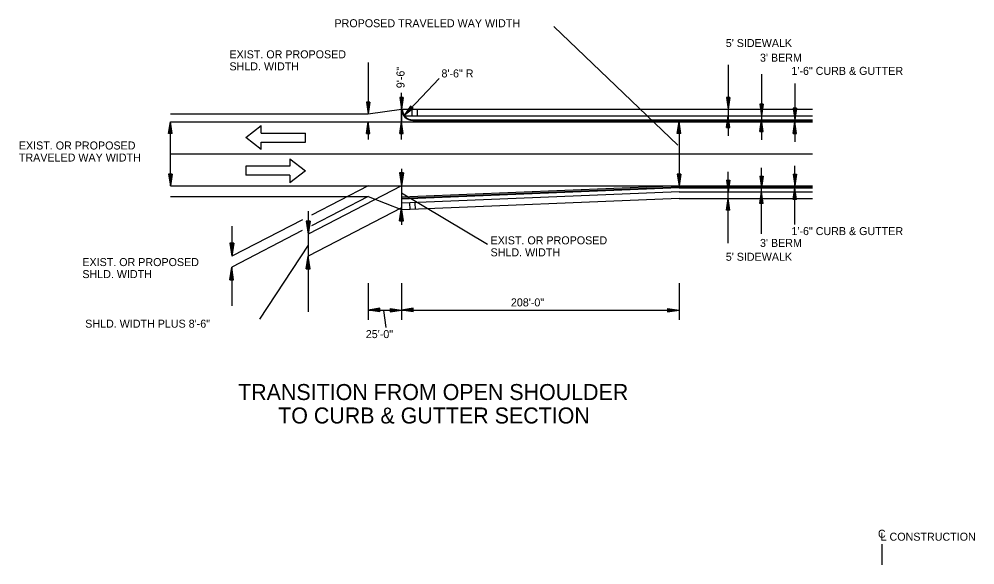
# Model space of a CAD drawing. Extents: x 635488 to 635865, y 290537 to 290973.
# Drawn here: x 635637.4 to 635709, y 290700.2 to 290741.1 of the extents above; entities that cross this region are included whole.
import ezdxf

# ---------------------------------------------------------------- set-up
doc = ezdxf.new("R2010")
doc.units = 0
for name, color, linetype in [('Default', 7, 'Continuous'), ('E_Existing ROW', 7, 'Continuous'), ('Level 13', 7, 'Continuous'), ('R_Border', 7, 'Continuous')]:
    doc.layers.add(name, color=color, linetype=linetype)

msp = doc.modelspace()

# ---------------------------------------------------------------- linework, layer by layer
at = {"layer": 'Default'}
for p, q in [((635677.431, 290740.568), (635686.72, 290731.689)), ((635663.524, 290737.876), (635663.524, 290734.024)), ((635690.499, 290737.702), (635690.499, 290732.374)), ((635692.999, 290737.002), (635692.999, 290732.074)), ((635695.499, 290736.302), (635695.499, 290731.924)), ((635663.524, 290734.024), (635666.024, 290734.374)), ((635666.024, 290734.374), (635696.824, 290734.374)), ((635666.787, 290734.374), (635666.787, 290733.874)), ((635667.187, 290734.374), (635667.187, 290733.874)), ((635648.699, 290734.024), (635663.524, 290734.024)), ((635648.699, 290733.424), (635696.824, 290733.424)), ((635648.699, 290728.624), (635648.699, 290733.424)), ((635663.524, 290733.424), (635663.524, 290732.112)), ((635666.187, 290733.874), (635696.824, 290733.874)), ((635666.874, 290733.574), (635696.824, 290733.574)), ((635666.874, 290733.524), (635696.824, 290733.524)), ((635648.699, 290731.024), (635696.824, 290731.024)), ((635692.999, 290725.045), (635692.999, 290729.974)), ((635695.499, 290725.745), (635695.499, 290730.124)), ((635690.499, 290724.345), (635690.499, 290729.674)), ((635648.699, 290728.624), (635686.824, 290728.624)), ((635686.824, 290728.624), (635666.02, 290727.773)), ((635686.824, 290728.524), (635666.024, 290727.674)), ((635686.824, 290728.473), (635666.026, 290727.624)), ((635686.822, 290728.624), (635696.824, 290728.624)), ((635686.824, 290728.524), (635696.824, 290728.524)), ((635686.824, 290728.474), (635696.824, 290728.474)), ((635648.699, 290727.824), (635663.524, 290727.824)), ((635663.524, 290727.824), (635666.059, 290726.824)), ((635686.824, 290728.173), (635666.038, 290727.324)), ((635686.824, 290728.174), (635696.824, 290728.174)), ((635686.824, 290727.673), (635666.059, 290726.824)), ((635666.658, 290726.849), (635666.638, 290727.348)), ((635667.058, 290726.865), (635667.038, 290727.365)), ((635686.824, 290727.674), (635696.824, 290727.674)), ((635663.524, 290721.342), (635663.524, 290718.581)), ((635666.024, 290721.342), (635666.024, 290718.581)), ((635686.824, 290721.342), (635686.824, 290718.581)), ((635663.524, 290719.323), (635666.024, 290719.323)), ((635664.861, 290718.01), (635664.707, 290719.285)), ((635666.024, 290719.323), (635686.824, 290719.323))]:
    msp.add_line(p, q, dxfattribs=at)
for radius in [0.85, 0.8]:
    msp.add_arc((635666.874, 290734.374), radius, 180, 270, dxfattribs=at)
at = {"layer": 'E_Existing ROW'}
for p, q in [((635668.836, 290736.674), (635666.187, 290733.874)), ((635666.024, 290732.112), (635666.024, 290735.608)), ((635663.393, 290734.898), (635663.524, 290734.024)), ((635663.655, 290734.898), (635663.393, 290734.898)), ((635663.414, 290734.898), (635663.524, 290734.169)), ((635663.437, 290734.898), (635663.524, 290734.32)), ((635663.459, 290734.898), (635663.524, 290734.466)), ((635663.481, 290734.898), (635663.524, 290734.614)), ((635663.504, 290734.898), (635663.524, 290734.76)), ((635663.655, 290734.898), (635663.524, 290734.024)), ((635663.567, 290734.898), (635663.524, 290734.614)), ((635663.611, 290734.898), (635663.524, 290734.32)), ((635663.634, 290734.898), (635663.524, 290734.169)), ((635663.59, 290734.898), (635663.524, 290734.466)), ((635663.544, 290734.898), (635663.524, 290734.76)), ((635665.893, 290735.248), (635666.024, 290734.374)), ((635666.155, 290735.248), (635665.893, 290735.248)), ((635665.914, 290735.248), (635666.024, 290734.519)), ((635665.937, 290735.248), (635666.024, 290734.67)), ((635665.959, 290735.248), (635666.024, 290734.816)), ((635665.981, 290735.248), (635666.024, 290734.964)), ((635666.004, 290735.248), (635666.024, 290735.11)), ((635666.155, 290735.248), (635666.024, 290734.374)), ((635666.067, 290735.248), (635666.024, 290734.964)), ((635666.111, 290735.248), (635666.024, 290734.67)), ((635666.134, 290735.248), (635666.024, 290734.519)), ((635666.09, 290735.248), (635666.024, 290734.816)), ((635666.044, 290735.248), (635666.024, 290735.11)), ((635690.368, 290735.248), (635690.499, 290734.374)), ((635690.63, 290735.248), (635690.368, 290735.248)), ((635690.39, 290735.248), (635690.499, 290734.519)), ((635690.412, 290735.248), (635690.499, 290734.67)), ((635690.434, 290735.248), (635690.499, 290734.816)), ((635690.457, 290735.248), (635690.499, 290734.964)), ((635690.479, 290735.248), (635690.499, 290735.11)), ((635690.63, 290735.248), (635690.499, 290734.374)), ((635690.542, 290735.248), (635690.499, 290734.964)), ((635690.586, 290735.248), (635690.499, 290734.67)), ((635690.609, 290735.248), (635690.499, 290734.519)), ((635690.565, 290735.248), (635690.499, 290734.816)), ((635690.519, 290735.248), (635690.499, 290735.11)), ((635666.024, 290734.374), (635666.024, 290733.424)), ((635666.692, 290734.598), (635666.186, 290733.873)), ((635666.882, 290734.418), (635666.186, 290733.873)), ((635666.708, 290734.583), (635666.286, 290733.978)), ((635666.867, 290734.433), (635666.286, 290733.978)), ((635666.724, 290734.568), (635666.39, 290734.088)), ((635666.85, 290734.448), (635666.39, 290734.088)), ((635666.74, 290734.553), (635666.491, 290734.195)), ((635666.835, 290734.463), (635666.491, 290734.195)), ((635666.756, 290734.537), (635666.593, 290734.302)), ((635666.818, 290734.479), (635666.593, 290734.302)), ((635666.882, 290734.418), (635666.692, 290734.598)), ((635666.773, 290734.522), (635666.692, 290734.408)), ((635666.802, 290734.494), (635666.692, 290734.408)), ((635692.868, 290734.748), (635692.999, 290733.874)), ((635693.13, 290734.748), (635692.868, 290734.748)), ((635692.89, 290734.748), (635692.999, 290734.019)), ((635692.912, 290734.748), (635692.999, 290734.17)), ((635692.934, 290734.748), (635692.999, 290734.316)), ((635692.957, 290734.748), (635692.999, 290734.464)), ((635692.979, 290734.748), (635692.999, 290734.61)), ((635693.13, 290734.748), (635692.999, 290733.874)), ((635693.042, 290734.748), (635692.999, 290734.464)), ((635693.086, 290734.748), (635692.999, 290734.17)), ((635693.109, 290734.748), (635692.999, 290734.019)), ((635693.065, 290734.748), (635692.999, 290734.316)), ((635693.019, 290734.748), (635692.999, 290734.61)), ((635695.368, 290734.448), (635695.499, 290733.574)), ((635695.63, 290734.448), (635695.368, 290734.448)), ((635695.39, 290734.448), (635695.499, 290733.719)), ((635695.412, 290734.448), (635695.499, 290733.87)), ((635695.434, 290734.448), (635695.499, 290734.016)), ((635695.457, 290734.448), (635695.499, 290734.164)), ((635695.479, 290734.448), (635695.499, 290734.31)), ((635695.63, 290734.448), (635695.499, 290733.574)), ((635695.542, 290734.448), (635695.499, 290734.164)), ((635695.586, 290734.448), (635695.499, 290733.87)), ((635695.609, 290734.448), (635695.499, 290733.719)), ((635695.565, 290734.448), (635695.499, 290734.016)), ((635695.519, 290734.448), (635695.499, 290734.31)), ((635648.568, 290732.549), (635648.699, 290733.424)), ((635648.83, 290732.549), (635648.699, 290733.424)), ((635663.393, 290732.549), (635663.524, 290733.424)), ((635663.655, 290732.549), (635663.524, 290733.424)), ((635665.893, 290732.549), (635666.024, 290733.424)), ((635666.155, 290732.549), (635666.024, 290733.424)), ((635686.693, 290732.549), (635686.824, 290733.424)), ((635686.824, 290733.424), (635686.824, 290728.624)), ((635686.955, 290732.549), (635686.824, 290733.424)), ((635690.368, 290732.999), (635690.499, 290733.874)), ((635690.39, 290732.999), (635690.499, 290733.728)), ((635690.412, 290732.999), (635690.499, 290733.577)), ((635690.434, 290732.999), (635690.499, 290733.431)), ((635690.63, 290732.999), (635690.499, 290733.874)), ((635690.609, 290732.999), (635690.499, 290733.728)), ((635690.586, 290732.999), (635690.499, 290733.577)), ((635690.565, 290732.999), (635690.499, 290733.431)), ((635692.868, 290732.699), (635692.999, 290733.574)), ((635692.89, 290732.699), (635692.999, 290733.428)), ((635693.13, 290732.699), (635692.999, 290733.574)), ((635693.109, 290732.699), (635692.999, 290733.428)), ((635695.368, 290732.549), (635695.499, 290733.424)), ((635695.63, 290732.549), (635695.499, 290733.424)), ((635648.589, 290732.549), (635648.699, 290733.278)), ((635648.612, 290732.549), (635648.699, 290733.127)), ((635648.633, 290732.549), (635648.699, 290732.981)), ((635648.656, 290732.549), (635648.699, 290732.833)), ((635648.808, 290732.549), (635648.699, 290733.278)), ((635648.785, 290732.549), (635648.699, 290733.127)), ((635648.764, 290732.549), (635648.699, 290732.981)), ((635648.741, 290732.549), (635648.699, 290732.833)), ((635654.341, 290732.251), (635655.509, 290733.151)), ((635655.509, 290732.588), (635655.509, 290733.151)), ((635663.414, 290732.549), (635663.524, 290733.278)), ((635663.437, 290732.549), (635663.524, 290733.127)), ((635663.459, 290732.549), (635663.524, 290732.981)), ((635663.481, 290732.549), (635663.524, 290732.833)), ((635663.634, 290732.549), (635663.524, 290733.278)), ((635663.611, 290732.549), (635663.524, 290733.127)), ((635663.59, 290732.549), (635663.524, 290732.981)), ((635663.567, 290732.549), (635663.524, 290732.833)), ((635665.914, 290732.549), (635666.024, 290733.278)), ((635665.937, 290732.549), (635666.024, 290733.127)), ((635665.959, 290732.549), (635666.024, 290732.981)), ((635665.981, 290732.549), (635666.024, 290732.833)), ((635666.134, 290732.549), (635666.024, 290733.278)), ((635666.111, 290732.549), (635666.024, 290733.127)), ((635666.09, 290732.549), (635666.024, 290732.981)), ((635666.067, 290732.549), (635666.024, 290732.833)), ((635686.714, 290732.549), (635686.824, 290733.278)), ((635686.737, 290732.549), (635686.824, 290733.127)), ((635686.759, 290732.549), (635686.824, 290732.981)), ((635686.781, 290732.549), (635686.824, 290732.833)), ((635686.934, 290732.549), (635686.824, 290733.278)), ((635686.911, 290732.549), (635686.824, 290733.127)), ((635686.89, 290732.549), (635686.824, 290732.981)), ((635686.867, 290732.549), (635686.824, 290732.833)), ((635690.368, 290732.999), (635690.63, 290732.999)), ((635690.457, 290732.999), (635690.499, 290733.283)), ((635690.479, 290732.999), (635690.499, 290733.137)), ((635690.542, 290732.999), (635690.499, 290733.283)), ((635690.519, 290732.999), (635690.499, 290733.137)), ((635692.868, 290732.699), (635693.13, 290732.699)), ((635692.912, 290732.699), (635692.999, 290733.277)), ((635692.934, 290732.699), (635692.999, 290733.131)), ((635692.957, 290732.699), (635692.999, 290732.983)), ((635692.979, 290732.699), (635692.999, 290732.837)), ((635693.086, 290732.699), (635692.999, 290733.277)), ((635693.065, 290732.699), (635692.999, 290733.131)), ((635693.042, 290732.699), (635692.999, 290732.983)), ((635693.019, 290732.699), (635692.999, 290732.837)), ((635695.39, 290732.549), (635695.499, 290733.278)), ((635695.412, 290732.549), (635695.499, 290733.127)), ((635695.434, 290732.549), (635695.499, 290732.981)), ((635695.457, 290732.549), (635695.499, 290732.833)), ((635695.609, 290732.549), (635695.499, 290733.278)), ((635695.586, 290732.549), (635695.499, 290733.127)), ((635695.565, 290732.549), (635695.499, 290732.981)), ((635695.542, 290732.549), (635695.499, 290732.833)), ((635648.83, 290732.549), (635648.568, 290732.549)), ((635648.679, 290732.549), (635648.699, 290732.687)), ((635648.718, 290732.549), (635648.699, 290732.687)), ((635655.509, 290731.351), (635654.341, 290732.251)), ((635655.509, 290732.588), (635658.819, 290732.588)), ((635658.819, 290731.913), (635658.819, 290732.588)), ((635663.393, 290732.549), (635663.655, 290732.549)), ((635663.504, 290732.549), (635663.524, 290732.687)), ((635663.544, 290732.549), (635663.524, 290732.687)), ((635665.893, 290732.549), (635666.155, 290732.549)), ((635666.004, 290732.549), (635666.024, 290732.687)), ((635666.044, 290732.549), (635666.024, 290732.687)), ((635686.955, 290732.549), (635686.693, 290732.549)), ((635686.804, 290732.549), (635686.824, 290732.687)), ((635686.844, 290732.549), (635686.824, 290732.687)), ((635695.368, 290732.549), (635695.63, 290732.549)), ((635695.479, 290732.549), (635695.499, 290732.687)), ((635695.519, 290732.549), (635695.499, 290732.687)), ((635655.509, 290731.913), (635658.819, 290731.913)), ((635655.509, 290731.351), (635655.509, 290731.913)), ((635657.651, 290730.658), (635657.651, 290730.096)), ((635657.651, 290730.658), (635658.819, 290729.758)), ((635657.651, 290730.096), (635654.341, 290730.096)), ((635654.341, 290730.096), (635654.341, 290729.421)), ((635666.02, 290729.906), (635666.02, 290728.624)), ((635648.568, 290729.498), (635648.699, 290728.624)), ((635648.83, 290729.498), (635648.568, 290729.498)), ((635648.589, 290729.498), (635648.699, 290728.769)), ((635648.612, 290729.498), (635648.699, 290728.92)), ((635648.633, 290729.498), (635648.699, 290729.066)), ((635648.656, 290729.498), (635648.699, 290729.214)), ((635648.679, 290729.498), (635648.699, 290729.36)), ((635648.83, 290729.498), (635648.699, 290728.624)), ((635648.741, 290729.498), (635648.699, 290729.214)), ((635648.785, 290729.498), (635648.699, 290728.92)), ((635648.808, 290729.498), (635648.699, 290728.769)), ((635648.764, 290729.498), (635648.699, 290729.066)), ((635648.718, 290729.498), (635648.699, 290729.36)), ((635657.651, 290729.421), (635654.341, 290729.421)), ((635658.819, 290729.758), (635657.651, 290728.858)), ((635657.651, 290729.421), (635657.651, 290728.858)), ((635665.873, 290729.606), (635666.02, 290728.624)), ((635666.167, 290729.606), (635665.873, 290729.606)), ((635665.897, 290729.606), (635666.02, 290728.787)), ((635665.922, 290729.606), (635666.02, 290728.956)), ((635665.946, 290729.606), (635666.02, 290729.121)), ((635665.972, 290729.606), (635666.02, 290729.287)), ((635665.998, 290729.606), (635666.02, 290729.451)), ((635666.167, 290729.606), (635666.02, 290728.624)), ((635666.068, 290729.606), (635666.02, 290729.287)), ((635666.118, 290729.606), (635666.02, 290728.956)), ((635666.143, 290729.606), (635666.02, 290728.787)), ((635666.094, 290729.606), (635666.02, 290729.121)), ((635666.042, 290729.606), (635666.02, 290729.451)), ((635686.693, 290729.498), (635686.824, 290728.624)), ((635686.955, 290729.498), (635686.693, 290729.498)), ((635686.714, 290729.498), (635686.824, 290728.769)), ((635686.737, 290729.498), (635686.824, 290728.92)), ((635686.759, 290729.498), (635686.824, 290729.066)), ((635686.781, 290729.498), (635686.824, 290729.215)), ((635686.804, 290729.498), (635686.824, 290729.36)), ((635686.955, 290729.498), (635686.824, 290728.624)), ((635686.867, 290729.498), (635686.824, 290729.215)), ((635686.911, 290729.498), (635686.824, 290728.92)), ((635686.934, 290729.498), (635686.824, 290728.769)), ((635686.89, 290729.498), (635686.824, 290729.066)), ((635686.844, 290729.498), (635686.824, 290729.36)), ((635692.868, 290729.348), (635692.999, 290728.474)), ((635692.868, 290729.348), (635693.13, 290729.348)), ((635692.89, 290729.348), (635692.999, 290728.619)), ((635692.912, 290729.348), (635692.999, 290728.77)), ((635692.934, 290729.348), (635692.999, 290728.916)), ((635692.957, 290729.348), (635692.999, 290729.064)), ((635692.979, 290729.348), (635692.999, 290729.21)), ((635693.13, 290729.348), (635692.999, 290728.474)), ((635693.042, 290729.348), (635692.999, 290729.064)), ((635693.086, 290729.348), (635692.999, 290728.77)), ((635693.109, 290729.348), (635692.999, 290728.619)), ((635693.065, 290729.348), (635692.999, 290728.916)), ((635693.019, 290729.348), (635692.999, 290729.21)), ((635695.368, 290729.498), (635695.499, 290728.624)), ((635695.368, 290729.498), (635695.63, 290729.498)), ((635695.39, 290729.498), (635695.499, 290728.769)), ((635695.412, 290729.498), (635695.499, 290728.92)), ((635695.434, 290729.498), (635695.499, 290729.066)), ((635695.457, 290729.498), (635695.499, 290729.214)), ((635695.479, 290729.498), (635695.499, 290729.36)), ((635695.63, 290729.498), (635695.499, 290728.624)), ((635695.542, 290729.498), (635695.499, 290729.214)), ((635695.586, 290729.498), (635695.499, 290728.92)), ((635695.609, 290729.498), (635695.499, 290728.769)), ((635695.565, 290729.498), (635695.499, 290729.066)), ((635695.519, 290729.498), (635695.499, 290729.36)), ((635666.02, 290728.624), (635659.018, 290725.012)), ((635663.519, 290728.624), (635659.275, 290726.434)), ((635666.02, 290728.624), (635666.02, 290725.714)), ((635690.368, 290729.048), (635690.499, 290728.174)), ((635690.368, 290729.048), (635690.63, 290729.048)), ((635690.39, 290729.048), (635690.499, 290728.319)), ((635690.412, 290729.048), (635690.499, 290728.47)), ((635690.434, 290729.048), (635690.499, 290728.616)), ((635690.457, 290729.048), (635690.499, 290728.764)), ((635690.479, 290729.048), (635690.499, 290728.91)), ((635690.63, 290729.048), (635690.499, 290728.174)), ((635690.542, 290729.048), (635690.499, 290728.764)), ((635690.586, 290729.048), (635690.499, 290728.47)), ((635690.609, 290729.048), (635690.499, 290728.319)), ((635690.565, 290729.048), (635690.499, 290728.616)), ((635690.519, 290729.048), (635690.499, 290728.91)), ((635695.368, 290727.599), (635695.499, 290728.474)), ((635695.63, 290727.599), (635695.499, 290728.474)), ((635663.519, 290727.824), (635659.279, 290725.637)), ((635666.02, 290728.109), (635672.455, 290724.272)), ((635692.868, 290727.299), (635692.999, 290728.174)), ((635692.89, 290727.299), (635692.999, 290728.028)), ((635692.912, 290727.299), (635692.999, 290727.877)), ((635692.934, 290727.299), (635692.999, 290727.731)), ((635693.13, 290727.299), (635692.999, 290728.174)), ((635693.109, 290727.299), (635692.999, 290728.028)), ((635693.086, 290727.299), (635692.999, 290727.877)), ((635693.065, 290727.299), (635692.999, 290727.731)), ((635695.39, 290727.599), (635695.499, 290728.328)), ((635695.412, 290727.599), (635695.499, 290728.177)), ((635695.434, 290727.599), (635695.499, 290728.031)), ((635695.457, 290727.599), (635695.499, 290727.883)), ((635695.479, 290727.599), (635695.499, 290727.737)), ((635695.609, 290727.599), (635695.499, 290728.328)), ((635695.586, 290727.599), (635695.499, 290728.177)), ((635695.565, 290727.599), (635695.499, 290728.031)), ((635695.542, 290727.599), (635695.499, 290727.883)), ((635695.519, 290727.599), (635695.499, 290727.737)), ((635666.02, 290726.972), (635659.018, 290723.36)), ((635665.876, 290726.012), (635666.02, 290726.972)), ((635666.164, 290726.012), (635666.02, 290726.972)), ((635690.368, 290726.799), (635690.499, 290727.674)), ((635690.39, 290726.799), (635690.499, 290727.528)), ((635690.412, 290726.799), (635690.499, 290727.377)), ((635690.434, 290726.799), (635690.499, 290727.231)), ((635690.457, 290726.799), (635690.499, 290727.083)), ((635690.63, 290726.799), (635690.499, 290727.674)), ((635690.609, 290726.799), (635690.499, 290727.528)), ((635690.586, 290726.799), (635690.499, 290727.377)), ((635690.565, 290726.799), (635690.499, 290727.231)), ((635690.542, 290726.799), (635690.499, 290727.083)), ((635693.13, 290727.299), (635692.868, 290727.299)), ((635692.957, 290727.299), (635692.999, 290727.583)), ((635692.979, 290727.299), (635692.999, 290727.437)), ((635693.042, 290727.299), (635692.999, 290727.583)), ((635693.019, 290727.299), (635692.999, 290727.437)), ((635695.63, 290727.599), (635695.368, 290727.599)), ((635659.018, 290726.729), (635659.018, 290722.102)), ((635665.9, 290726.012), (635666.02, 290726.812)), ((635665.924, 290726.012), (635666.02, 290726.647)), ((635665.948, 290726.012), (635666.02, 290726.487)), ((635665.974, 290726.012), (635666.02, 290726.324)), ((635666.14, 290726.012), (635666.02, 290726.812)), ((635666.116, 290726.012), (635666.02, 290726.647)), ((635666.092, 290726.012), (635666.02, 290726.487)), ((635666.066, 290726.012), (635666.02, 290726.324)), ((635690.63, 290726.799), (635690.368, 290726.799)), ((635690.479, 290726.799), (635690.499, 290726.937)), ((635690.519, 290726.799), (635690.499, 290726.937)), ((635658.603, 290726.088), (635653.293, 290723.349)), ((635653.293, 290725.614), (635653.293, 290723.349)), ((635658.87, 290725.994), (635659.018, 290725.012)), ((635659.165, 290725.994), (635658.87, 290725.994)), ((635658.894, 290725.994), (635659.018, 290725.175)), ((635658.92, 290725.994), (635659.018, 290725.344)), ((635658.944, 290725.994), (635659.018, 290725.509)), ((635658.97, 290725.994), (635659.018, 290725.675)), ((635658.995, 290725.994), (635659.018, 290725.839)), ((635659.165, 290725.994), (635659.018, 290725.012)), ((635659.066, 290725.994), (635659.018, 290725.675)), ((635659.115, 290725.994), (635659.018, 290725.344)), ((635659.141, 290725.994), (635659.018, 290725.175)), ((635659.091, 290725.994), (635659.018, 290725.509)), ((635659.04, 290725.994), (635659.018, 290725.839)), ((635665.876, 290726.012), (635666.164, 290726.012)), ((635665.998, 290726.012), (635666.02, 290726.164)), ((635666.042, 290726.012), (635666.02, 290726.164)), ((635658.586, 290725.279), (635653.293, 290722.549)), ((635653.146, 290724.331), (635653.293, 290723.349)), ((635653.441, 290724.331), (635653.146, 290724.331)), ((635653.17, 290724.331), (635653.293, 290723.512)), ((635653.196, 290724.331), (635653.293, 290723.682)), ((635653.22, 290724.331), (635653.293, 290723.847)), ((635653.245, 290724.331), (635653.293, 290724.013)), ((635653.271, 290724.331), (635653.293, 290724.176)), ((635653.441, 290724.331), (635653.293, 290723.349)), ((635653.341, 290724.331), (635653.293, 290724.013)), ((635653.391, 290724.331), (635653.293, 290723.682)), ((635653.417, 290724.331), (635653.293, 290723.512)), ((635653.367, 290724.331), (635653.293, 290723.847)), ((635653.316, 290724.331), (635653.293, 290724.176)), ((635659.018, 290724.195), (635655.377, 290718.63)), ((635658.874, 290722.4), (635659.018, 290723.36)), ((635658.898, 290722.4), (635659.018, 290723.2)), ((635658.922, 290722.4), (635659.018, 290723.035)), ((635658.946, 290722.4), (635659.018, 290722.875)), ((635658.971, 290722.4), (635659.018, 290722.712)), ((635659.162, 290722.4), (635659.018, 290723.36)), ((635659.138, 290722.4), (635659.018, 290723.2)), ((635659.114, 290722.4), (635659.018, 290723.035)), ((635659.09, 290722.4), (635659.018, 290722.875)), ((635659.064, 290722.4), (635659.018, 290722.712)), ((635653.149, 290721.589), (635653.293, 290722.549)), ((635653.173, 290721.589), (635653.293, 290722.389)), ((635653.197, 290721.589), (635653.293, 290722.224)), ((635653.221, 290721.589), (635653.293, 290722.064)), ((635653.293, 290722.549), (635653.293, 290719.63)), ((635653.437, 290721.589), (635653.293, 290722.549)), ((635653.413, 290721.589), (635653.293, 290722.389)), ((635653.389, 290721.589), (635653.293, 290722.224)), ((635653.365, 290721.589), (635653.293, 290722.064)), ((635658.874, 290722.4), (635659.162, 290722.4)), ((635658.995, 290722.4), (635659.018, 290722.552)), ((635659.04, 290722.4), (635659.018, 290722.552)), ((635659.018, 290722.102), (635659.018, 290719.183)), ((635653.149, 290721.589), (635653.437, 290721.589)), ((635653.247, 290721.589), (635653.293, 290721.901)), ((635653.271, 290721.589), (635653.293, 290721.741)), ((635653.34, 290721.589), (635653.293, 290721.901)), ((635653.316, 290721.589), (635653.293, 290721.741)), ((635664.398, 290719.454), (635663.524, 290719.323)), ((635664.398, 290719.192), (635663.524, 290719.323)), ((635664.398, 290719.433), (635663.669, 290719.323)), ((635664.398, 290719.213), (635663.669, 290719.323)), ((635664.398, 290719.41), (635663.82, 290719.323)), ((635664.398, 290719.236), (635663.82, 290719.323)), ((635664.398, 290719.389), (635663.967, 290719.323)), ((635664.398, 290719.258), (635663.967, 290719.323)), ((635664.398, 290719.366), (635664.115, 290719.323)), ((635664.398, 290719.28), (635664.115, 290719.323)), ((635664.398, 290719.343), (635664.26, 290719.323)), ((635664.398, 290719.303), (635664.26, 290719.323)), ((635664.398, 290719.192), (635664.398, 290719.454)), ((635665.17, 290719.451), (635666.024, 290719.323)), ((635665.17, 290719.451), (635665.17, 290719.195)), ((635665.17, 290719.43), (635665.882, 290719.323)), ((635665.17, 290719.409), (635665.735, 290719.323)), ((635665.17, 290719.387), (635665.593, 290719.323)), ((635665.17, 290719.364), (635665.447, 290719.323)), ((635665.17, 290719.343), (635665.305, 290719.323)), ((635665.17, 290719.195), (635666.024, 290719.323)), ((635665.17, 290719.282), (635665.447, 290719.323)), ((635665.17, 290719.238), (635665.735, 290719.323)), ((635665.17, 290719.216), (635665.882, 290719.323)), ((635665.17, 290719.259), (635665.593, 290719.323)), ((635665.17, 290719.303), (635665.305, 290719.323)), ((635666.898, 290719.454), (635666.024, 290719.323)), ((635666.898, 290719.192), (635666.024, 290719.323)), ((635666.898, 290719.433), (635666.169, 290719.323)), ((635666.898, 290719.213), (635666.169, 290719.323)), ((635666.898, 290719.41), (635666.32, 290719.323)), ((635666.898, 290719.236), (635666.32, 290719.323)), ((635666.898, 290719.389), (635666.467, 290719.323)), ((635666.898, 290719.258), (635666.467, 290719.323)), ((635666.898, 290719.366), (635666.615, 290719.323)), ((635666.898, 290719.28), (635666.615, 290719.323)), ((635666.898, 290719.343), (635666.76, 290719.323)), ((635666.898, 290719.303), (635666.76, 290719.323)), ((635666.898, 290719.192), (635666.898, 290719.454)), ((635685.97, 290719.451), (635686.824, 290719.323)), ((635685.97, 290719.451), (635685.97, 290719.195)), ((635685.97, 290719.43), (635686.682, 290719.323)), ((635685.97, 290719.409), (635686.535, 290719.323)), ((635685.97, 290719.387), (635686.393, 290719.323)), ((635685.97, 290719.364), (635686.247, 290719.323)), ((635685.97, 290719.343), (635686.105, 290719.323)), ((635685.97, 290719.195), (635686.824, 290719.323)), ((635685.97, 290719.282), (635686.247, 290719.323)), ((635685.97, 290719.238), (635686.535, 290719.323)), ((635685.97, 290719.216), (635686.682, 290719.323)), ((635685.97, 290719.259), (635686.393, 290719.323)), ((635685.97, 290719.303), (635686.105, 290719.323))]:
    msp.add_line(p, q, dxfattribs=at)
at = {"layer": 'R_Border'}
msp.add_line((635702.051, 290700.232), (635702.051, 290701.786), dxfattribs=at)

# ---------------------------------------------------------------- texts
at = {"layer": 'E_Existing ROW'}
for s, rotation, p in [('PROPOSED TRAVELED WAY WIDTH', 360, (635660.996, 290740.512)), ('EXIST. OR PROPOSED', 360, (635653.123, 290738.184)), ('SHLD. WIDTH', 360, (635653.123, 290737.284)), ('9\'-6"', 90, (635666.246, 290735.947)), ('EXIST. OR PROPOSED', 360, (635637.341, 290731.353)), ('TRAVELED WAY WIDTH', 360, (635637.341, 290730.453)), ('EXIST. OR PROPOSED', 360, (635672.695, 290724.247)), ('SHLD. WIDTH', 360, (635672.695, 290723.347)), ('EXIST. OR PROPOSED', 360, (635642.099, 290722.618)), ('SHLD. WIDTH', 360, (635642.099, 290721.718)), ('208\'-0"', 360, (635674.22, 290719.598)), ('SHLD. WIDTH PLUS 8\'-6"', 360, (635642.312, 290718.002)), ('25\'-0"', 360, (635663.344, 290717.223))]:
    msp.add_text(s, height=0.6, rotation=rotation, dxfattribs=at).set_placement(p)
for s, height, p in [("5' SIDEWALK", 0.6, (635690.327, 290739.03)), ("3' BERM", 0.6, (635692.89, 290737.931)), ('8\'-6" R', 0.6, (635669.016, 290736.752)), ('1\'-6" CURB & GUTTER', 0.6, (635695.246, 290736.943)), ('1\'-6" CURB & GUTTER', 0.6, (635695.246, 290724.94)), ("3' BERM", 0.6, (635692.89, 290724.052)), ("5' SIDEWALK", 0.6, (635690.327, 290723.016)), ('TRANSITION FROM OPEN SHOULDER', 1.2, (635653.774, 290712.581)), ('TO CURB & GUTTER SECTION', 1.2, (635656.777, 290710.825))]:
    msp.add_text(s, height=height, dxfattribs=at).set_placement(p)
at = {"layer": 'Level 13'}
for s, p in [('C', (635701.732, 290702.264)), ('L CONSTRUCTION', (635701.931, 290702.042))]:
    msp.add_text(s, height=0.6, dxfattribs=at).set_placement(p)

doc.saveas('drawing.dxf')
